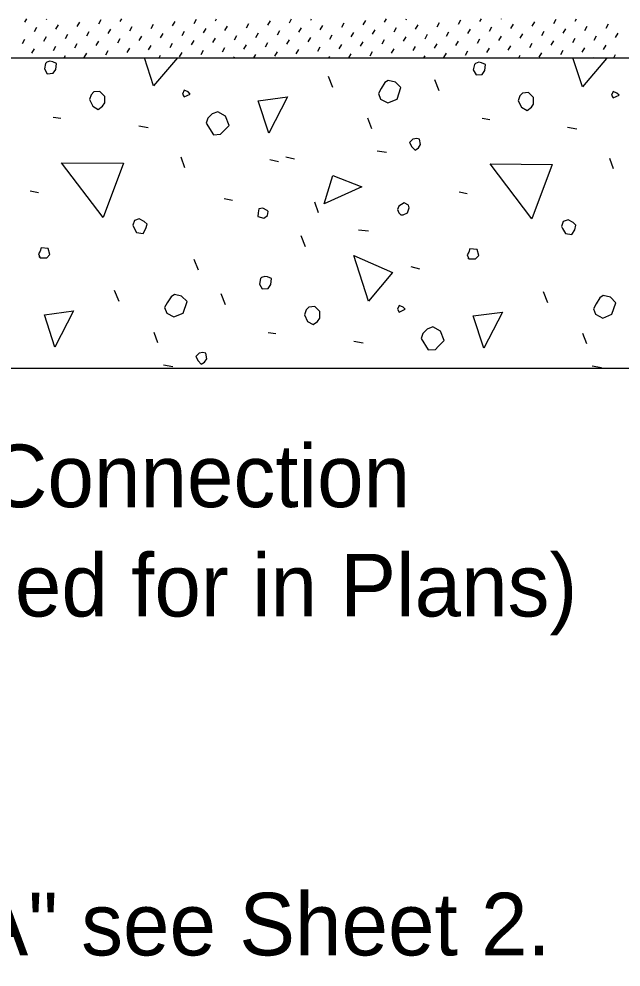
# Model space of a CAD drawing. Extents: x 0.5 to 40.8, y 1 to 25.8.
# Drawn here: x 35.979 to 37.921, y 8.632 to 11.685 of the extents above; entities that cross this region are included whole.
import ezdxf

# ---------------------------------------------------------------- set-up
doc = ezdxf.new("R2010")
doc.units = 0
for name, color, linetype in [('Dimension', 7, 'Continuous'), ('Miscellaneous', 7, 'Continuous'), ('TrafBarrierConc', 7, 'Continuous')]:
    doc.layers.add(name, color=color, linetype=linetype)

msp = doc.modelspace()

# ---------------------------------------------------------------- linework, layer by layer
at = {"layer": 'Miscellaneous'}
for p, q in [((35.9987, 11.6748), (36.0045, 11.6848)), ((36.0679, 11.6829), (36.069, 11.6848)), ((36.0984, 11.6524), (36.1065, 11.6664)), ((36.1676, 11.6605), (36.1757, 11.6745)), ((36.2368, 11.6686), (36.2449, 11.6826)), ((36.3059, 11.6767), (36.3106, 11.6848)), ((36.4056, 11.6543), (36.4137, 11.6683)), ((36.4748, 11.6624), (36.4829, 11.6764)), ((36.5439, 11.6705), (36.552, 11.6845)), ((36.6131, 11.6786), (36.6167, 11.6848)), ((36.7128, 11.6562), (36.7209, 11.6702)), ((36.782, 11.6643), (36.7901, 11.6783)), ((36.8511, 11.6724), (36.8583, 11.6848)), ((36.9203, 11.6805), (36.9228, 11.6848)), ((36.9508, 11.6499), (36.9589, 11.6639)), ((37.02, 11.658), (37.0281, 11.672)), ((37.0891, 11.6661), (37.0972, 11.6801)), ((37.1583, 11.6742), (37.1644, 11.6848)), ((37.2275, 11.6823), (37.2289, 11.6848)), ((37.258, 11.6518), (37.2661, 11.6658)), ((37.3272, 11.6599), (37.3353, 11.6739)), ((37.3963, 11.668), (37.4044, 11.682)), ((37.4655, 11.6761), (37.4705, 11.6848)), ((37.5347, 11.6842), (37.535, 11.6848)), ((37.5652, 11.6537), (37.5733, 11.6677)), ((37.6344, 11.6618), (37.6425, 11.6758)), ((37.7035, 11.6699), (37.7116, 11.6839)), ((37.7727, 11.678), (37.7766, 11.6848)), ((37.8724, 11.6556), (37.8805, 11.6696)), ((36.0293, 11.6443), (36.0374, 11.6583)), ((36.129, 11.6219), (36.1371, 11.6359)), ((36.1981, 11.63), (36.2062, 11.644)), ((36.2673, 11.6381), (36.2754, 11.6521)), ((36.3364, 11.6462), (36.3445, 11.6602)), ((36.4361, 11.6238), (36.4442, 11.6378)), ((36.5053, 11.6319), (36.5134, 11.6459)), ((36.5745, 11.64), (36.5826, 11.654)), ((36.6436, 11.6481), (36.6517, 11.6621)), ((36.7433, 11.6256), (36.7514, 11.6396)), ((36.8125, 11.6337), (36.8206, 11.6477)), ((36.8817, 11.6418), (36.8898, 11.6558)), ((36.9814, 11.6194), (36.9895, 11.6334)), ((37.0505, 11.6275), (37.0586, 11.6415)), ((37.1197, 11.6356), (37.1278, 11.6496)), ((37.1888, 11.6437), (37.1969, 11.6577)), ((37.2885, 11.6213), (37.2966, 11.6353)), ((37.3577, 11.6294), (37.3658, 11.6434)), ((37.4269, 11.6375), (37.435, 11.6515)), ((37.496, 11.6456), (37.5041, 11.6596)), ((37.5957, 11.6232), (37.6038, 11.6372)), ((37.6649, 11.6313), (37.673, 11.6453)), ((37.7341, 11.6394), (37.7422, 11.6534)), ((37.8032, 11.6475), (37.8113, 11.6615)), ((37.9029, 11.625), (37.911, 11.639)), ((35.9906, 11.6057), (35.9987, 11.6197)), ((36.0598, 11.6138), (36.0679, 11.6278)), ((36.1595, 11.5913), (36.1676, 11.6053)), ((36.2286, 11.5994), (36.2368, 11.6134)), ((36.2978, 11.6076), (36.3059, 11.6215)), ((36.367, 11.6157), (36.3751, 11.6296)), ((36.4667, 11.5932), (36.4748, 11.6072)), ((36.5358, 11.6013), (36.5439, 11.6153)), ((36.605, 11.6094), (36.6131, 11.6234)), ((36.6742, 11.6175), (36.6823, 11.6315)), ((36.7739, 11.5951), (36.782, 11.6091)), ((36.843, 11.6032), (36.8511, 11.6172)), ((36.9122, 11.6113), (36.9203, 11.6253)), ((37.0119, 11.5889), (37.02, 11.6029)), ((37.081, 11.597), (37.0891, 11.611)), ((37.1502, 11.6051), (37.1583, 11.6191)), ((37.2194, 11.6132), (37.2275, 11.6272)), ((37.3191, 11.5908), (37.3272, 11.6048)), ((37.3882, 11.5989), (37.3963, 11.6129)), ((37.4574, 11.607), (37.4655, 11.621)), ((37.5266, 11.6151), (37.5347, 11.6291)), ((37.6263, 11.5926), (37.6344, 11.6066)), ((37.6954, 11.6007), (37.7035, 11.6147)), ((37.7646, 11.6088), (37.7727, 11.6228)), ((37.8337, 11.6169), (37.8418, 11.6309)), ((36.0212, 11.5751), (36.0293, 11.5891)), ((36.0903, 11.5832), (36.0984, 11.5972)), ((36.19, 11.5608), (36.1981, 11.5748)), ((36.2592, 11.5689), (36.2673, 11.5829)), ((36.3283, 11.577), (36.3364, 11.591)), ((36.3975, 11.5851), (36.4056, 11.5991)), ((36.4972, 11.5627), (36.5053, 11.5767)), ((36.5664, 11.5708), (36.5745, 11.5848)), ((36.6355, 11.5789), (36.6436, 11.5929)), ((36.7047, 11.587), (36.7128, 11.601)), ((36.8044, 11.5646), (36.8125, 11.5786)), ((36.8736, 11.5727), (36.8817, 11.5867)), ((36.9427, 11.5808), (36.9508, 11.5948)), ((37.0432, 11.5598), (37.0505, 11.5723)), ((37.1116, 11.5665), (37.1197, 11.5804)), ((37.1807, 11.5746), (37.1888, 11.5885)), ((37.2499, 11.5827), (37.258, 11.5966)), ((37.3496, 11.5602), (37.3577, 11.5742)), ((37.4188, 11.5683), (37.4269, 11.5823)), ((37.4879, 11.5764), (37.496, 11.5904)), ((37.5571, 11.5845), (37.5652, 11.5985)), ((37.6568, 11.5621), (37.6649, 11.5761)), ((37.7259, 11.5702), (37.7341, 11.5842)), ((37.7951, 11.5783), (37.8032, 11.5923)), ((37.8643, 11.5864), (37.8724, 11.6004)), ((36.125, 11.5598), (36.129, 11.5667)), ((36.3666, 11.5598), (36.367, 11.5605)), ((36.4311, 11.5598), (36.4361, 11.5686)), ((36.6727, 11.5598), (36.6742, 11.5624)), ((36.7371, 11.5598), (36.7433, 11.5705)), ((36.9788, 11.5598), (36.9814, 11.5642)), ((37.2849, 11.5598), (37.2885, 11.5661)), ((37.5265, 11.5598), (37.5266, 11.5599)), ((37.591, 11.5598), (37.5957, 11.568)), ((37.8326, 11.5598), (37.8337, 11.5618)), ((37.8971, 11.5598), (37.9029, 11.5699)), ((36.9915, 11.4639), (36.9774, 11.4993)), ((37.3345, 11.4533), (37.3204, 11.4887)), ((36.09, 11.3685), (36.1147, 11.3649)), ((37.1171, 11.3313), (37.1047, 11.3649)), ((37.4724, 11.3649), (37.4971, 11.3614)), ((36.3658, 11.3402), (36.3958, 11.3349)), ((37.7482, 11.3366), (37.7782, 11.3313)), ((36.5142, 11.2058), (36.5019, 11.2394)), ((36.8395, 11.2412), (36.8678, 11.2341)), ((37.1347, 11.2606), (37.1648, 11.2553)), ((36.7883, 11.2324), (36.8165, 11.2253)), ((37.8966, 11.2023), (37.8843, 11.2359)), ((36.0157, 11.1316), (36.0423, 11.1263)), ((37.3981, 11.1281), (37.4246, 11.1227)), ((36.6415, 11.1068), (36.668, 11.1015)), ((36.9456, 11.0609), (36.9332, 11.0945)), ((37.0746, 11.0061), (37.1065, 11.0025)), ((36.9032, 10.9513), (36.889, 10.9866)), ((36.5584, 10.8753), (36.5443, 10.9106)), ((37.2426, 10.8876), (37.2709, 10.8806)), ((36.3021, 10.7745), (36.288, 10.8099)), ((36.6451, 10.7639), (36.6309, 10.7992)), ((37.6845, 10.771), (37.6704, 10.8063)), ((36.4276, 10.6419), (36.4153, 10.6755)), ((36.7829, 10.6755), (36.8077, 10.672)), ((37.81, 10.6384), (37.7976, 10.672)), ((37.0587, 10.6472), (37.0888, 10.6419)), ((36.4453, 10.5712), (36.4754, 10.5659)), ((37.8277, 10.5677), (37.8578, 10.5624))]:
    msp.add_line(p, q, dxfattribs=at)
for points in [[(36.0617, 11.524), (36.0705, 11.5081), (36.09, 11.5099), (36.0988, 11.5223), (36.1006, 11.5417), (36.0882, 11.547), (36.0794, 11.5488), (36.0688, 11.5452), (36.0652, 11.5417), (36.0617, 11.524)], [(36.4135, 11.4692), (36.384, 11.5598)], [(36.4901, 11.5598), (36.4135, 11.4692)], [(37.4441, 11.5205), (37.4529, 11.5046), (37.4724, 11.5064), (37.4812, 11.5187), (37.483, 11.5382), (37.4706, 11.5435), (37.4618, 11.5452), (37.4512, 11.5417), (37.4476, 11.5382), (37.4441, 11.5205)], [(37.7959, 11.4657), (37.7653, 11.5598)], [(37.8687, 11.5598), (37.8737, 11.5576), (37.7959, 11.4657)], [(37.1453, 11.4268), (37.1683, 11.4144), (37.1984, 11.4268), (37.2107, 11.4639), (37.1931, 11.4816), (37.1701, 11.4869), (37.1595, 11.4798), (37.1471, 11.4604), (37.1383, 11.4445), (37.1453, 11.4268)], [(36.2067, 11.425), (36.2173, 11.4038), (36.2349, 11.3932), (36.2491, 11.4038), (36.2562, 11.4144), (36.2562, 11.4356), (36.2402, 11.4516), (36.2208, 11.4498), (36.212, 11.4409), (36.2067, 11.425)], [(36.5125, 11.4339), (36.5319, 11.4427), (36.5249, 11.4498), (36.5125, 11.4551), (36.5072, 11.4427), (36.5125, 11.4339)], [(37.8949, 11.4303), (37.9143, 11.4392), (37.9072, 11.4463), (37.8949, 11.4516), (37.8896, 11.4392), (37.8949, 11.4303)], [(36.7847, 11.3172), (36.7511, 11.4215), (36.8448, 11.4339), (36.7847, 11.3172)], [(37.5891, 11.4215), (37.5997, 11.4003), (37.6173, 11.3897), (37.6315, 11.4003), (37.6385, 11.4109), (37.6385, 11.4321), (37.6226, 11.448), (37.6032, 11.4463), (37.5944, 11.4374), (37.5891, 11.4215)], [(36.5832, 11.349), (36.6062, 11.3119), (36.6292, 11.3137), (36.638, 11.3225), (36.6574, 11.342), (36.6451, 11.372), (36.6203, 11.3861), (36.6026, 11.3791), (36.5885, 11.3649), (36.5832, 11.349)], [(37.2461, 11.273), (37.2567, 11.2624), (37.2673, 11.2695), (37.2744, 11.2801), (37.2709, 11.2978), (37.262, 11.2995), (37.2496, 11.2978), (37.239, 11.2872), (37.2461, 11.273)], [(36.2509, 11.045), (36.1165, 11.2217), (36.3163, 11.22), (36.2509, 11.045)], [(37.6332, 11.0414), (37.4989, 11.2182), (37.6987, 11.2164), (37.6332, 11.0414)], [(36.9633, 11.0892), (36.9915, 11.1811), (37.0852, 11.144), (36.9633, 11.0892)], [(37.2107, 11.0538), (37.2178, 11.0538), (37.232, 11.0609), (37.2373, 11.0768), (37.2355, 11.0856), (37.2214, 11.0927), (37.2037, 11.0821), (37.2001, 11.0715), (37.2037, 11.0609), (37.2107, 11.0538)], [(36.7494, 11.0485), (36.7688, 11.0432), (36.7812, 11.052), (36.7829, 11.0644), (36.7794, 11.0679), (36.7653, 11.075), (36.7529, 11.0733), (36.7511, 11.0609), (36.7494, 11.0485)], [(36.3498, 11.0131), (36.3587, 10.9972), (36.3799, 10.9937), (36.3887, 11.0096), (36.3923, 11.0238), (36.3834, 11.0326), (36.3675, 11.0414), (36.3516, 11.0361), (36.3463, 11.0202), (36.3498, 11.0131)], [(37.7322, 11.0096), (37.7411, 10.9937), (37.7623, 10.9902), (37.7711, 11.0061), (37.7747, 11.0202), (37.7658, 11.0291), (37.7499, 11.0379), (37.734, 11.0326), (37.7287, 11.0167), (37.7322, 11.0096)], [(36.0476, 10.9159), (36.0688, 10.9159), (36.0794, 10.9265), (36.0741, 10.946), (36.0511, 10.9477), (36.0476, 10.9371), (36.0423, 10.9283), (36.0476, 10.9159), (36.044, 10.9195)], [(37.43, 10.9124), (37.4512, 10.9124), (37.4618, 10.923), (37.4565, 10.9424), (37.4335, 10.9442), (37.43, 10.9336), (37.4246, 10.9248), (37.43, 10.9124), (37.4264, 10.9159)], [(37.1065, 10.7763), (37.0587, 10.923), (37.1842, 10.8682), (37.1065, 10.7763)], [(36.7547, 10.8311), (36.7635, 10.8152), (36.7829, 10.8169), (36.7918, 10.8293), (36.7936, 10.8487), (36.7812, 10.854), (36.7723, 10.8558), (36.7617, 10.8523), (36.7582, 10.8487), (36.7547, 10.8311)], [(36.4559, 10.7374), (36.4789, 10.725), (36.5089, 10.7374), (36.5213, 10.7745), (36.5036, 10.7922), (36.4807, 10.7975), (36.4701, 10.7904), (36.4577, 10.771), (36.4488, 10.7551), (36.4559, 10.7374)], [(37.8383, 10.7338), (37.8613, 10.7215), (37.8913, 10.7338), (37.9037, 10.771), (37.886, 10.7886), (37.8631, 10.7939), (37.8524, 10.7869), (37.8401, 10.7674), (37.8312, 10.7515), (37.8383, 10.7338)], [(36.8996, 10.7321), (36.9102, 10.7109), (36.9279, 10.7003), (36.942, 10.7109), (36.9491, 10.7215), (36.9491, 10.7427), (36.9332, 10.7586), (36.9138, 10.7568), (36.9049, 10.748), (36.8996, 10.7321)], [(37.2054, 10.7409), (37.2249, 10.7498), (37.2178, 10.7568), (37.2054, 10.7621), (37.2001, 10.7498), (37.2054, 10.7409)], [(36.0953, 10.6278), (36.0617, 10.7321), (36.1554, 10.7444), (36.0953, 10.6278)], [(37.4777, 10.6242), (37.4441, 10.7285), (37.5378, 10.7409), (37.4777, 10.6242)], [(37.2762, 10.6561), (37.2991, 10.6189), (37.3221, 10.6207), (37.331, 10.6295), (37.3504, 10.649), (37.338, 10.679), (37.3133, 10.6932), (37.2956, 10.6861), (37.2815, 10.672), (37.2762, 10.6561)], [(36.5567, 10.5836), (36.5673, 10.573), (36.5779, 10.58), (36.585, 10.5907), (36.5814, 10.6083), (36.5726, 10.6101), (36.5602, 10.6083), (36.5496, 10.5977), (36.5567, 10.5836)]]:
    msp.add_lwpolyline(points, dxfattribs=at)
at = {"layer": 'TrafBarrierConc'}
for p, q in [((23.987, 11.5598), (39.8181, 11.5598)), ((23.987, 10.5598), (39.8181, 10.5598))]:
    msp.add_line(p, q, dxfattribs=at)

# ---------------------------------------------------------------- texts
at = {"layer": 'Dimension'}
for s, p in [('Guardrail Connection', (34.6929, 10.1125)), ('(When called for in Plans)', (34.6929, 9.7605)), ('  For Section A-A, End View B-B and Detail "A" see Sheet 2.', (30.5047, 8.669))]:
    msp.add_text(s, height=0.2016, dxfattribs=at).set_placement(p)

doc.saveas('drawing.dxf')
